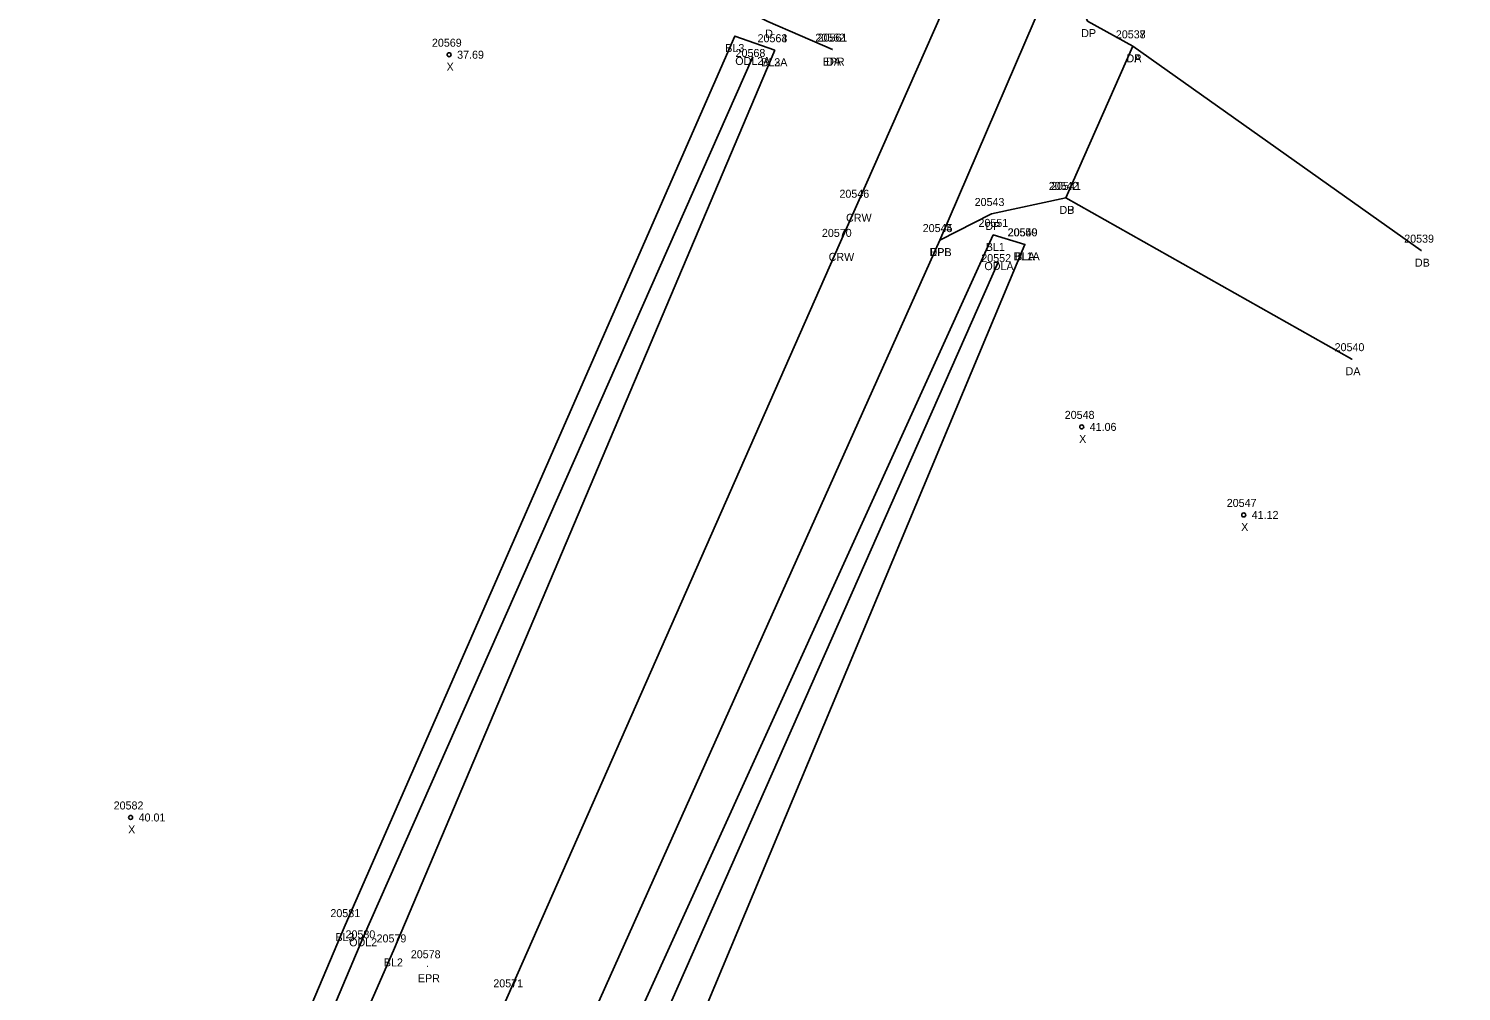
# Model space of a CAD drawing. Extents: x 2432729 to 2433340, y 684958 to 688103.
# Drawn here: x 2432758.2 to 2432937.3, y 685076.6 to 685196.9 of the extents above; entities that cross this region are included whole.
import ezdxf

# ---------------------------------------------------------------- set-up
doc = ezdxf.new("R2010")
doc.units = 0
for name, color, linetype in [('RD_DTM_BkLn1', 7, 'Continuous'), ('RD_EX_Driveway', 7, 'Continuous'), ('RD_EX_Driveway_txCode', 7, 'Continuous'), ('RD_EX_H2O', 7, 'Continuous'), ('RD_EX_H2O_txCode', 7, 'Continuous'), ('RD_EX_Road', 7, 'Continuous'), ('RD_EX_Road_txCode', 7, 'Continuous'), ('RD_Sketch8', 7, 'Continuous'), ('RD_SMD_Locator', 7, 'Continuous'), ('RD_SMD_Misc', 7, 'Continuous')]:
    doc.layers.add(name, color=color, linetype=linetype)

msp = doc.modelspace()

# ---------------------------------------------------------------- linework, layer by layer
at = {"layer": 'RD_DTM_BkLn1'}
for points in [[(2433067.41, 685690.62), (2433052.49, 685638.4), (2433035.04, 685585.7), (2433018.41, 685541.16), (2432999.85, 685493.3), (2432978.77, 685442.62), (2432938.71, 685349.86), (2432898.27, 685257.39), (2432861.69, 685174.74), (2432859.51, 685169.85), (2432818.13, 685076.09), (2432777.09, 684983.43)], [(2432851.47, 685194.17), (2432846.48, 685195.94), (2432797.77, 685084.86), (2432758.22, 684991.42)], [(2432851.47, 685194.17), (2432803.82, 685081.7), (2432763.08, 684988.71)], [(2432882.72, 685169.92), (2432878.77, 685171.1), (2432832.54, 685069.35), (2432792.27, 684977.69)], [(2432882.72, 685169.92), (2432839.17, 685065.84), (2432799.03, 684974.06)]]:
    msp.add_lwpolyline(points, dxfattribs=at)
at = {"layer": 'RD_EX_Driveway'}
for p, q in [((2432896.21, 685194.66), (2432932.26, 685169.13)), ((2432923.6, 685155.57), (2432887.83, 685175.72))]:
    msp.add_line(p, q, dxfattribs=at)
for points in [[(2432887.37, 685205.96), (2432890.55, 685197.81), (2432896.21, 685194.66), (2432887.83, 685175.72), (2432878.57, 685173.71), (2432872.08, 685170.45)], [(2432858.68, 685194.25), (2432850.59, 685197.75), (2432837.25, 685204.61)]]:
    msp.add_lwpolyline(points, dxfattribs=at)
at = {"layer": 'RD_EX_H2O'}
for points in [[(2432848.72, 685193.33), (2432799.98, 685083.21), (2432760.65, 684990.18)], [(2432879.4, 685167.7), (2432835.28, 685067.92), (2432795.13, 684976.25)]]:
    msp.add_lwpolyline(points, dxfattribs=at)
at = {"layer": 'RD_EX_Road'}
msp.add_lwpolyline([(2433077.66, 685687.92), (2433062.23, 685635.7), (2433044.84, 685582.68), (2433028.22, 685537.07), (2433009.68, 685489.83), (2432988.53, 685438.27), (2432948.62, 685345.62), (2432907.86, 685252.74), (2432887.37, 685205.96), (2432872.08, 685170.45), (2432827.85, 685071.69), (2432787.31, 684979.59)], dxfattribs=at)
at = {"layer": 'RD_SMD_Locator'}
for centre, radius in [((2432846.48, 685195.94), 0.001), ((2432810.77, 685193.61), 0.25), ((2432848.72, 685193.33), 0.001), ((2432851.47, 685194.17), 0.001), ((2432851.47, 685194.17), 0.001), ((2432858.68, 685194.25), 0.001), ((2432858.68, 685194.25), 0.001), ((2432896.21, 685194.66), 0.001), ((2432896.21, 685194.66), 0.001), ((2432887.83, 685175.72), 0.001), ((2432887.83, 685175.72), 0.001), ((2432861.69, 685174.74), 0.001), ((2432878.57, 685173.71), 0.001), ((2432872.08, 685170.45), 0.001), ((2432872.08, 685170.45), 0.001), ((2432878.77, 685171.1), 0.001), ((2432882.72, 685169.92), 0.001), ((2432882.72, 685169.92), 0.001), ((2432859.51, 685169.85), 0.001), ((2432932.26, 685169.13), 0.001), ((2432879.4, 685167.7), 0.001), ((2432923.6, 685155.57), 0.001), ((2432889.83, 685147.11), 0.25), ((2432910.08, 685136.11), 0.25), ((2432770.96, 685098.31), 0.25), ((2432797.77, 685084.86), 0.001), ((2432799.98, 685083.21), 0.001), ((2432803.82, 685081.7), 0.001), ((2432808.1, 685079.72), 0.001)]:
    msp.add_circle(centre, radius, dxfattribs=at)

# ---------------------------------------------------------------- texts
at = {"layer": 'RD_EX_Driveway_txCode'}
for s, p in [('D', (2432850.28, 685195.75)), ('DP', (2432889.77, 685195.81)), ('20562', (2432856.54, 685195.25)), ('20537', (2432894.1, 685195.66)), ('20538', (2432894.1, 685195.66)), ('DA', (2432857.89, 685192.25)), ('DA', (2432895.42, 685192.66)), ('DP', (2432895.43, 685192.66)), ('20542', (2432885.72, 685176.72)), ('20541', (2432886, 685176.72)), ('20543', (2432876.45, 685174.71)), ('DB', (2432887.05, 685173.72)), ('DP', (2432887.05, 685173.72)), ('20544', (2432869.96, 685171.45)), ('DP', (2432877.79, 685171.71)), ('20539', (2432930.14, 685170.13)), ('DPB', (2432870.82, 685168.45)), ('DB', (2432931.48, 685167.13)), ('20540', (2432921.44, 685156.57)), ('DA', (2432922.81, 685153.57))]:
    msp.add_text(s, height=1, dxfattribs=at).set_placement(p)
at = {"layer": 'RD_EX_H2O_txCode'}
for s, p in [('ODL2A', (2432846.53, 685192.33)), ('20568', (2432846.57, 685193.33)), ('20552', (2432877.28, 685167.7)), ('ODLA', (2432877.67, 685166.7)), ('20580', (2432797.82, 685083.21)), ('ODL2', (2432798.28, 685082.21))]:
    msp.add_text(s, height=1, dxfattribs=at).set_placement(p)
at = {"layer": 'RD_EX_Road_txCode'}
for s, p in [('20561', (2432856.82, 685195.25)), ('EPR', (2432857.45, 685192.25)), ('20545', (2432869.96, 685171.45)), ('EPL', (2432870.87, 685168.45)), ('20578', (2432805.98, 685080.72)), ('EPR', (2432806.87, 685077.72))]:
    msp.add_text(s, height=1, dxfattribs=at).set_placement(p)
at = {"layer": 'RD_Sketch8'}
for s, p in [('20569', (2432808.62, 685194.61)), ('37.69', (2432811.77, 685193.11)), ('X', (2432810.45, 685191.61)), ('20548', (2432887.71, 685148.11)), ('41.06', (2432890.83, 685146.61)), ('X', (2432889.51, 685145.11)), ('20547', (2432907.96, 685137.11)), ('41.12', (2432911.08, 685135.61)), ('X', (2432909.76, 685134.11)), ('20582', (2432768.84, 685099.31)), ('40.01', (2432771.96, 685097.81)), ('X', (2432770.65, 685096.31))]:
    msp.add_text(s, height=1, dxfattribs=at).set_placement(p)
at = {"layer": 'RD_SMD_Misc'}
for s, p in [('BL3', (2432845.28, 685193.94)), ('20563', (2432849.32, 685195.17)), ('20564', (2432849.32, 685195.17)), ('BL2A', (2432849.77, 685192.17)), ('BL3A', (2432849.77, 685192.17)), ('20546', (2432859.55, 685175.74)), ('CRW', (2432860.38, 685172.74)), ('20570', (2432857.36, 685170.85)), ('20551', (2432876.93, 685172.1)), ('20550', (2432880.56, 685170.92)), ('20549', (2432880.6, 685170.92)), ('BL1', (2432877.84, 685169.1)), ('CRW', (2432858.2, 685167.85)), ('BL1A', (2432881.31, 685167.92)), ('BLA', (2432881.47, 685167.92)), ('20581', (2432795.93, 685085.86)), ('BL3', (2432796.56, 685082.86)), ('20579', (2432801.7, 685082.7)), ('BL2', (2432802.61, 685079.7)), ('20571', (2432816.29, 685077.09))]:
    msp.add_text(s, height=1, dxfattribs=at).set_placement(p)

doc.saveas('drawing.dxf')
